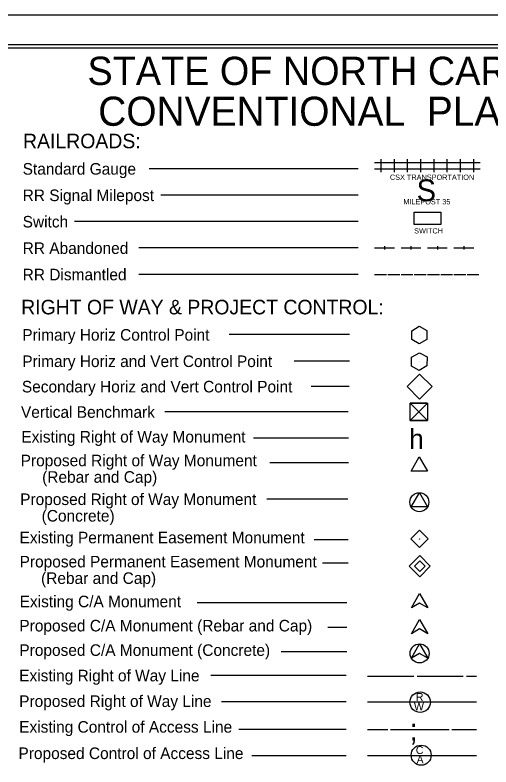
# Model space of a CAD drawing. Extents: x 1669394 to 1671078, y 697867 to 698967.
# Drawn here: x 1669956 to 1670317, y 698398 to 698967 of the extents above; entities that cross this region are included whole.
import ezdxf

# ---------------------------------------------------------------- set-up
doc = ezdxf.new("R2010")
doc.units = 0
for name, color, linetype in [('Default', 7, 'Continuous'), ('Prop ROW Permanent Easement CELL', 7, 'Continuous'), ('Sheet Cutting Line CELL', 7, 'Continuous'), ('Sheet Plot Border Inside CELL', 7, 'Continuous'), ('Sheet Plot Border Outside CELL', 7, 'Continuous'), ('Sheet Symbology CELL', 7, 'Continuous')]:
    doc.layers.add(name, color=color, linetype=linetype)

msp = doc.modelspace()

# ---------------------------------------------------------------- linework, layer by layer
at = {"layer": 'Default'}
for p, q in [((1670262.66, 698724.71), (1670262.66, 698724.71)), ((1670262.65, 698704.74), (1670262.65, 698704.74)), ((1670262.79, 698685.66), (1670262.79, 698685.66)), ((1670262.29, 698666.66), (1670262.29, 698666.66)), ((1670262.75, 698570.44), (1670262.75, 698570.44))]:
    msp.add_line(p, q, dxfattribs=at)
for points in [[(1670262.66, 698718.05), (1670256.87, 698721.35), (1670256.87, 698728), (1670262.66, 698731.36), (1670268.46, 698728.07), (1670268.46, 698721.35), (1670262.66, 698718.05)], [(1670268.76, 698673.14), (1670255.79, 698660.17), (1670262.28, 698666.65), (1670268.76, 698660.17), (1670255.79, 698673.14)], [(1670262.28, 698666.65), (1670268.76, 698673.14), (1670255.79, 698673.14), (1670262.28, 698666.65)], [(1670262.28, 698666.65), (1670255.79, 698660.17), (1670268.76, 698660.17), (1670262.28, 698666.65)]]:
    msp.add_lwpolyline(points, dxfattribs=at)
for points in [[(1670256.82, 698708.12), (1670262.69, 698711.39), (1670268.55, 698708.16), (1670268.46, 698701.44), (1670262.6, 698698.03), (1670256.82, 698701.3)], [(1670253.38, 698685.7), (1670262.84, 698695.15), (1670272.31, 698685.68), (1670262.85, 698676.22)], [(1670255.79, 698673.14), (1670268.76, 698673.14), (1670268.76, 698660.17), (1670255.79, 698660.17)], [(1670256.26, 698570.44), (1670262.75, 698576.94), (1670269.25, 698570.44), (1670262.75, 698563.95)]]:
    msp.add_lwpolyline(points, close=True, dxfattribs=at)
msp.add_circle((1670262.75, 698570.44), 0.126, dxfattribs=at)
at = {"layer": 'Prop ROW Permanent Easement CELL'}
msp.add_line((1670262.93, 698549.84), (1670262.93, 698549.84), dxfattribs=at)
for points in [[(1670262.93, 698557.89), (1670270.98, 698549.84), (1670262.93, 698541.79), (1670254.88, 698549.84)], [(1670262.93, 698553.86), (1670266.96, 698549.84), (1670262.93, 698545.81), (1670258.9, 698549.84)]]:
    msp.add_lwpolyline(points, close=True, dxfattribs=at)
at = {"layer": 'Sheet Cutting Line CELL'}
msp.add_line((1671077.79, 698967.01), (1669393.79, 698967.01), dxfattribs=at)
at = {"layer": 'Sheet Plot Border Inside CELL'}
msp.add_lwpolyline([(1669406.79, 697889.46), (1671073.29, 697889.46), (1671073.29, 698944.56), (1669406.79, 698944.56)], close=True, dxfattribs=at)
at = {"layer": 'Sheet Plot Border Outside CELL'}
msp.add_lwpolyline([(1669393.79, 697867.01), (1671077.79, 697867.01), (1671077.79, 698967.01), (1669393.79, 698967.01)], close=True, dxfattribs=at)
at = {"layer": 'Sheet Symbology CELL'}
for p, q in [((1670228.82, 698855.46), (1670238.82, 698855.46)), ((1670233.82, 698847.96), (1670233.82, 698857.96)), ((1670238.82, 698855.46), (1670248.82, 698855.46)), ((1670243.82, 698847.96), (1670243.82, 698857.96)), ((1670248.82, 698855.46), (1670258.82, 698855.46)), ((1670253.82, 698847.96), (1670253.82, 698857.96)), ((1670258.82, 698855.46), (1670268.82, 698855.46)), ((1670263.82, 698847.96), (1670263.82, 698857.96)), ((1670268.82, 698855.46), (1670278.82, 698855.46)), ((1670273.82, 698847.96), (1670273.82, 698857.96)), ((1670278.82, 698855.46), (1670288.82, 698855.46)), ((1670283.82, 698847.96), (1670283.82, 698857.96)), ((1670288.82, 698855.46), (1670298.82, 698855.46)), ((1670293.82, 698847.96), (1670293.82, 698857.96)), ((1670298.82, 698855.46), (1670308.82, 698855.46)), ((1670303.82, 698847.96), (1670303.82, 698857.96)), ((1670216.42, 698850.7), (1670058.01, 698850.7)), ((1670228.82, 698850.46), (1670238.82, 698850.46)), ((1670238.82, 698850.46), (1670248.82, 698850.46)), ((1670248.82, 698850.46), (1670258.82, 698850.46)), ((1670258.82, 698850.46), (1670268.82, 698850.46)), ((1670268.82, 698850.46), (1670278.82, 698850.46)), ((1670278.82, 698850.46), (1670288.82, 698850.46)), ((1670288.82, 698850.46), (1670298.82, 698850.46)), ((1670298.82, 698850.46), (1670308.82, 698850.46)), ((1670216.42, 698830.7), (1670066.87, 698830.7)), ((1670216.42, 698810.7), (1670001.51, 698810.7)), ((1670236.32, 698791.95), (1670236.32, 698789.45)), ((1670256.32, 698791.95), (1670256.32, 698789.45)), ((1670276.32, 698791.95), (1670276.32, 698789.45)), ((1670296.32, 698791.95), (1670296.32, 698789.45)), ((1670216.42, 698790.7), (1670050.26, 698790.7)), ((1670228.82, 698790.7), (1670243.82, 698790.7)), ((1670248.82, 698790.7), (1670263.82, 698790.7)), ((1670268.82, 698790.7), (1670283.82, 698790.7)), ((1670288.82, 698790.7), (1670303.82, 698790.7)), ((1670216.42, 698770.7), (1670050.26, 698770.7)), ((1670216.42, 698770.7), (1670050.26, 698770.7)), ((1670228.82, 698770.7), (1670237.82, 698770.7)), ((1670238.82, 698770.7), (1670247.82, 698770.7)), ((1670248.82, 698770.7), (1670257.82, 698770.7)), ((1670258.82, 698770.7), (1670267.82, 698770.7)), ((1670268.82, 698770.7), (1670277.82, 698770.7)), ((1670278.82, 698770.7), (1670287.82, 698770.7)), ((1670288.82, 698770.7), (1670297.82, 698770.7)), ((1670298.82, 698770.7), (1670307.82, 698770.7)), ((1670209.73, 698725.08), (1670118.7, 698725.08)), ((1670209.73, 698705.08), (1670167.81, 698705.08)), ((1670209.42, 698685.87), (1670180.86, 698685.87)), ((1670208.73, 698666.65), (1670069.89, 698666.65)), ((1670209.04, 698646.67), (1670136.99, 698646.67)), ((1670209.14, 698627.89), (1670149.41, 698627.89)), ((1670262.66, 698625.27), (1670262.66, 698625.27)), ((1670208.64, 698600.48), (1670147.15, 698600.48)), ((1670262.67, 698598.21), (1670262.67, 698598.21)), ((1670208.72, 698569.79), (1670182.92, 698569.79)), ((1670208.72, 698552.17), (1670189.44, 698552.17)), ((1670256.66, 698518.26), (1670262.91, 698529.06)), ((1670262.91, 698529.06), (1670269.16, 698518.26)), ((1670207.72, 698521.95), (1670094.49, 698521.95)), ((1670262.91, 698521.86), (1670256.66, 698518.26)), ((1670269.16, 698518.26), (1670262.91, 698521.86)), ((1670256.63, 698498.65), (1670262.88, 698509.45)), ((1670262.88, 698509.45), (1670269.13, 698498.65)), ((1670207.82, 698503.42), (1670193.25, 698503.42)), ((1670262.88, 698502.25), (1670256.63, 698498.65)), ((1670269.13, 698498.65), (1670262.88, 698502.25)), ((1670256.63, 698480.14), (1670262.88, 698490.94)), ((1670262.88, 698490.94), (1670269.13, 698480.14)), ((1670207.82, 698484.91), (1670158.15, 698484.91)), ((1670262.88, 698483.74), (1670256.63, 698480.14)), ((1670269.13, 698480.14), (1670262.88, 698483.74)), ((1670207.38, 698467.13), (1670104.87, 698467.13)), ((1670223.41, 698466.56), (1670258.41, 698466.56)), ((1670260.91, 698466.56), (1670295.91, 698466.56)), ((1670298.41, 698466.56), (1670305.91, 698466.56)), ((1670207.38, 698447.13), (1670112.86, 698447.13)), ((1670223.41, 698447.01), (1670305.91, 698447.01)), ((1670207.38, 698426.01), (1670126.06, 698426.01)), ((1670223.41, 698426.01), (1670238.88, 698426.01)), ((1670240.88, 698426.01), (1670285.29, 698426.01)), ((1670287.29, 698426.01), (1670305.91, 698426.01)), ((1670207.38, 698406.19), (1670135.74, 698406.19)), ((1670223.41, 698406.57), (1670305.91, 698406.57))]:
    msp.add_line(p, q, dxfattribs=at)
for points in [[(1671060.79, 698942.01), (1669560.79, 698942.01), (1669560.79, 697893.03), (1671060.79, 697893.03)], [(1670258.82, 698817.66), (1670278.82, 698817.66), (1670278.82, 698808.56), (1670258.82, 698808.56)], [(1670256.41, 698621.67), (1670262.66, 698632.47), (1670268.91, 698621.67)], [(1670256.42, 698594.61), (1670262.67, 698605.41), (1670268.92, 698594.61)]]:
    msp.add_lwpolyline(points, close=True, dxfattribs=at)
for centre, radius in [((1670262.67, 698598.21), 7.2), ((1670262.88, 698483.74), 7.2), ((1670263.27, 698446.8), 7.75), ((1670264.06, 698406.67), 7.58)]:
    msp.add_circle(centre, radius, dxfattribs=at)

# ---------------------------------------------------------------- texts
for s, height, p in [('STATE OF NORTH CAROLINA, DIVISION OF HIGHWAYS', 21.419, (1670011.36, 698914.05)), ('CONVENTIONAL  PLAN SHEET SYMBOLS', 22.0323, (1670019.48, 698883.17)), ('RAILROADS:', 11, (1669962.54, 698866.15)), ('Standard Gauge', 8.75, (1669962.26, 698846.17)), ('S', 16.5, (1670260.58, 698826.07)), ('RR Signal Milepost', 8.75, (1669962.26, 698826.17)), ('Switch', 8.75, (1669962.26, 698806.17)), ('RR Abandoned', 8.75, (1669962.26, 698786.17)), ('RR Dismantled', 8.75, (1669962.26, 698766.17)), ('RIGHT OF WAY & PROJECT CONTROL:', 11, (1669961.13, 698740.42)), ('Primary Horiz Control Point', 8.75, (1669961.98, 698720.53)), ('Primary Horiz and Vert Control Point', 8.75, (1669961.98, 698700.53)), ('Secondary Horiz and Vert Control Point', 8.75, (1669961.67, 698681.32)), ('Vertical Benchmark', 8.75, (1669960.98, 698662.1)), ('Existing Right of Way Monument', 8.75, (1669961.29, 698643.39)), ('h', 15, (1670254.89, 698638.49)), ('Proposed Right of Way Monument', 8.75, (1669960.77, 698625.42)), ('     (Rebar and Cap)', 8.75, (1669960.77, 698612.92)), ('Proposed Right of Way Monument', 8.75, (1669960.39, 698596.06)), ('     (Concrete)', 8.75, (1669960.39, 698583.56)), ('Existing Permanent Easement Monument', 8.75, (1669959.91, 698567.07)), ('Proposed Permanent Easement Monument', 8.75, (1669959.95, 698548.84)), ('     (Rebar and Cap)', 8.75, (1669959.95, 698536.34)), ('Existing C/A Monument', 8.75, (1669959.97, 698518.67)), ('Proposed C/A Monument (Rebar and Cap)', 8.75, (1669959.77, 698500.36)), ('Proposed C/A Monument (Concrete)', 8.75, (1669959.77, 698481.86)), ('Existing Right of Way Line', 8.75, (1669959.63, 698462.58)), ('Proposed Right of Way Line', 8.75, (1669959.63, 698443.2)), ('R', 6.08, (1670259.93, 698447.71)), ('W', 6.08, (1670258.55, 698440.56)), ('Existing Control of Access Line', 8.75, (1669959.63, 698423.74)), (';', 16.5, (1670255.21, 698417.82)), ('Proposed Control of Access Line', 8.75, (1669959.09, 698403.76)), ('C', 5.94, (1670260.03, 698407.57)), ('A', 5.94, (1670260.62, 698400.43))]:
    msp.add_text(s, height=height, dxfattribs=at).set_placement(p)
for s, p in [('CSX TRANSPORTATION', (1670240.38, 698842.22)), ('MILEPOST 35', (1670250.57, 698823.65)), ('SWITCH', (1670258.77, 698801.65))]:
    msp.add_text(s, height=4, rotation=360, dxfattribs=at).set_placement(p)

doc.saveas('drawing.dxf')
